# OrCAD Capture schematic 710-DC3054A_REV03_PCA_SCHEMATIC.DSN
size B; title: 3.3V TO 1.8V AT 3A, 4A, 6A AND 6.6MHz LOW EMI BUCK REGULATOR IN A 0.47cm² SOLUTION
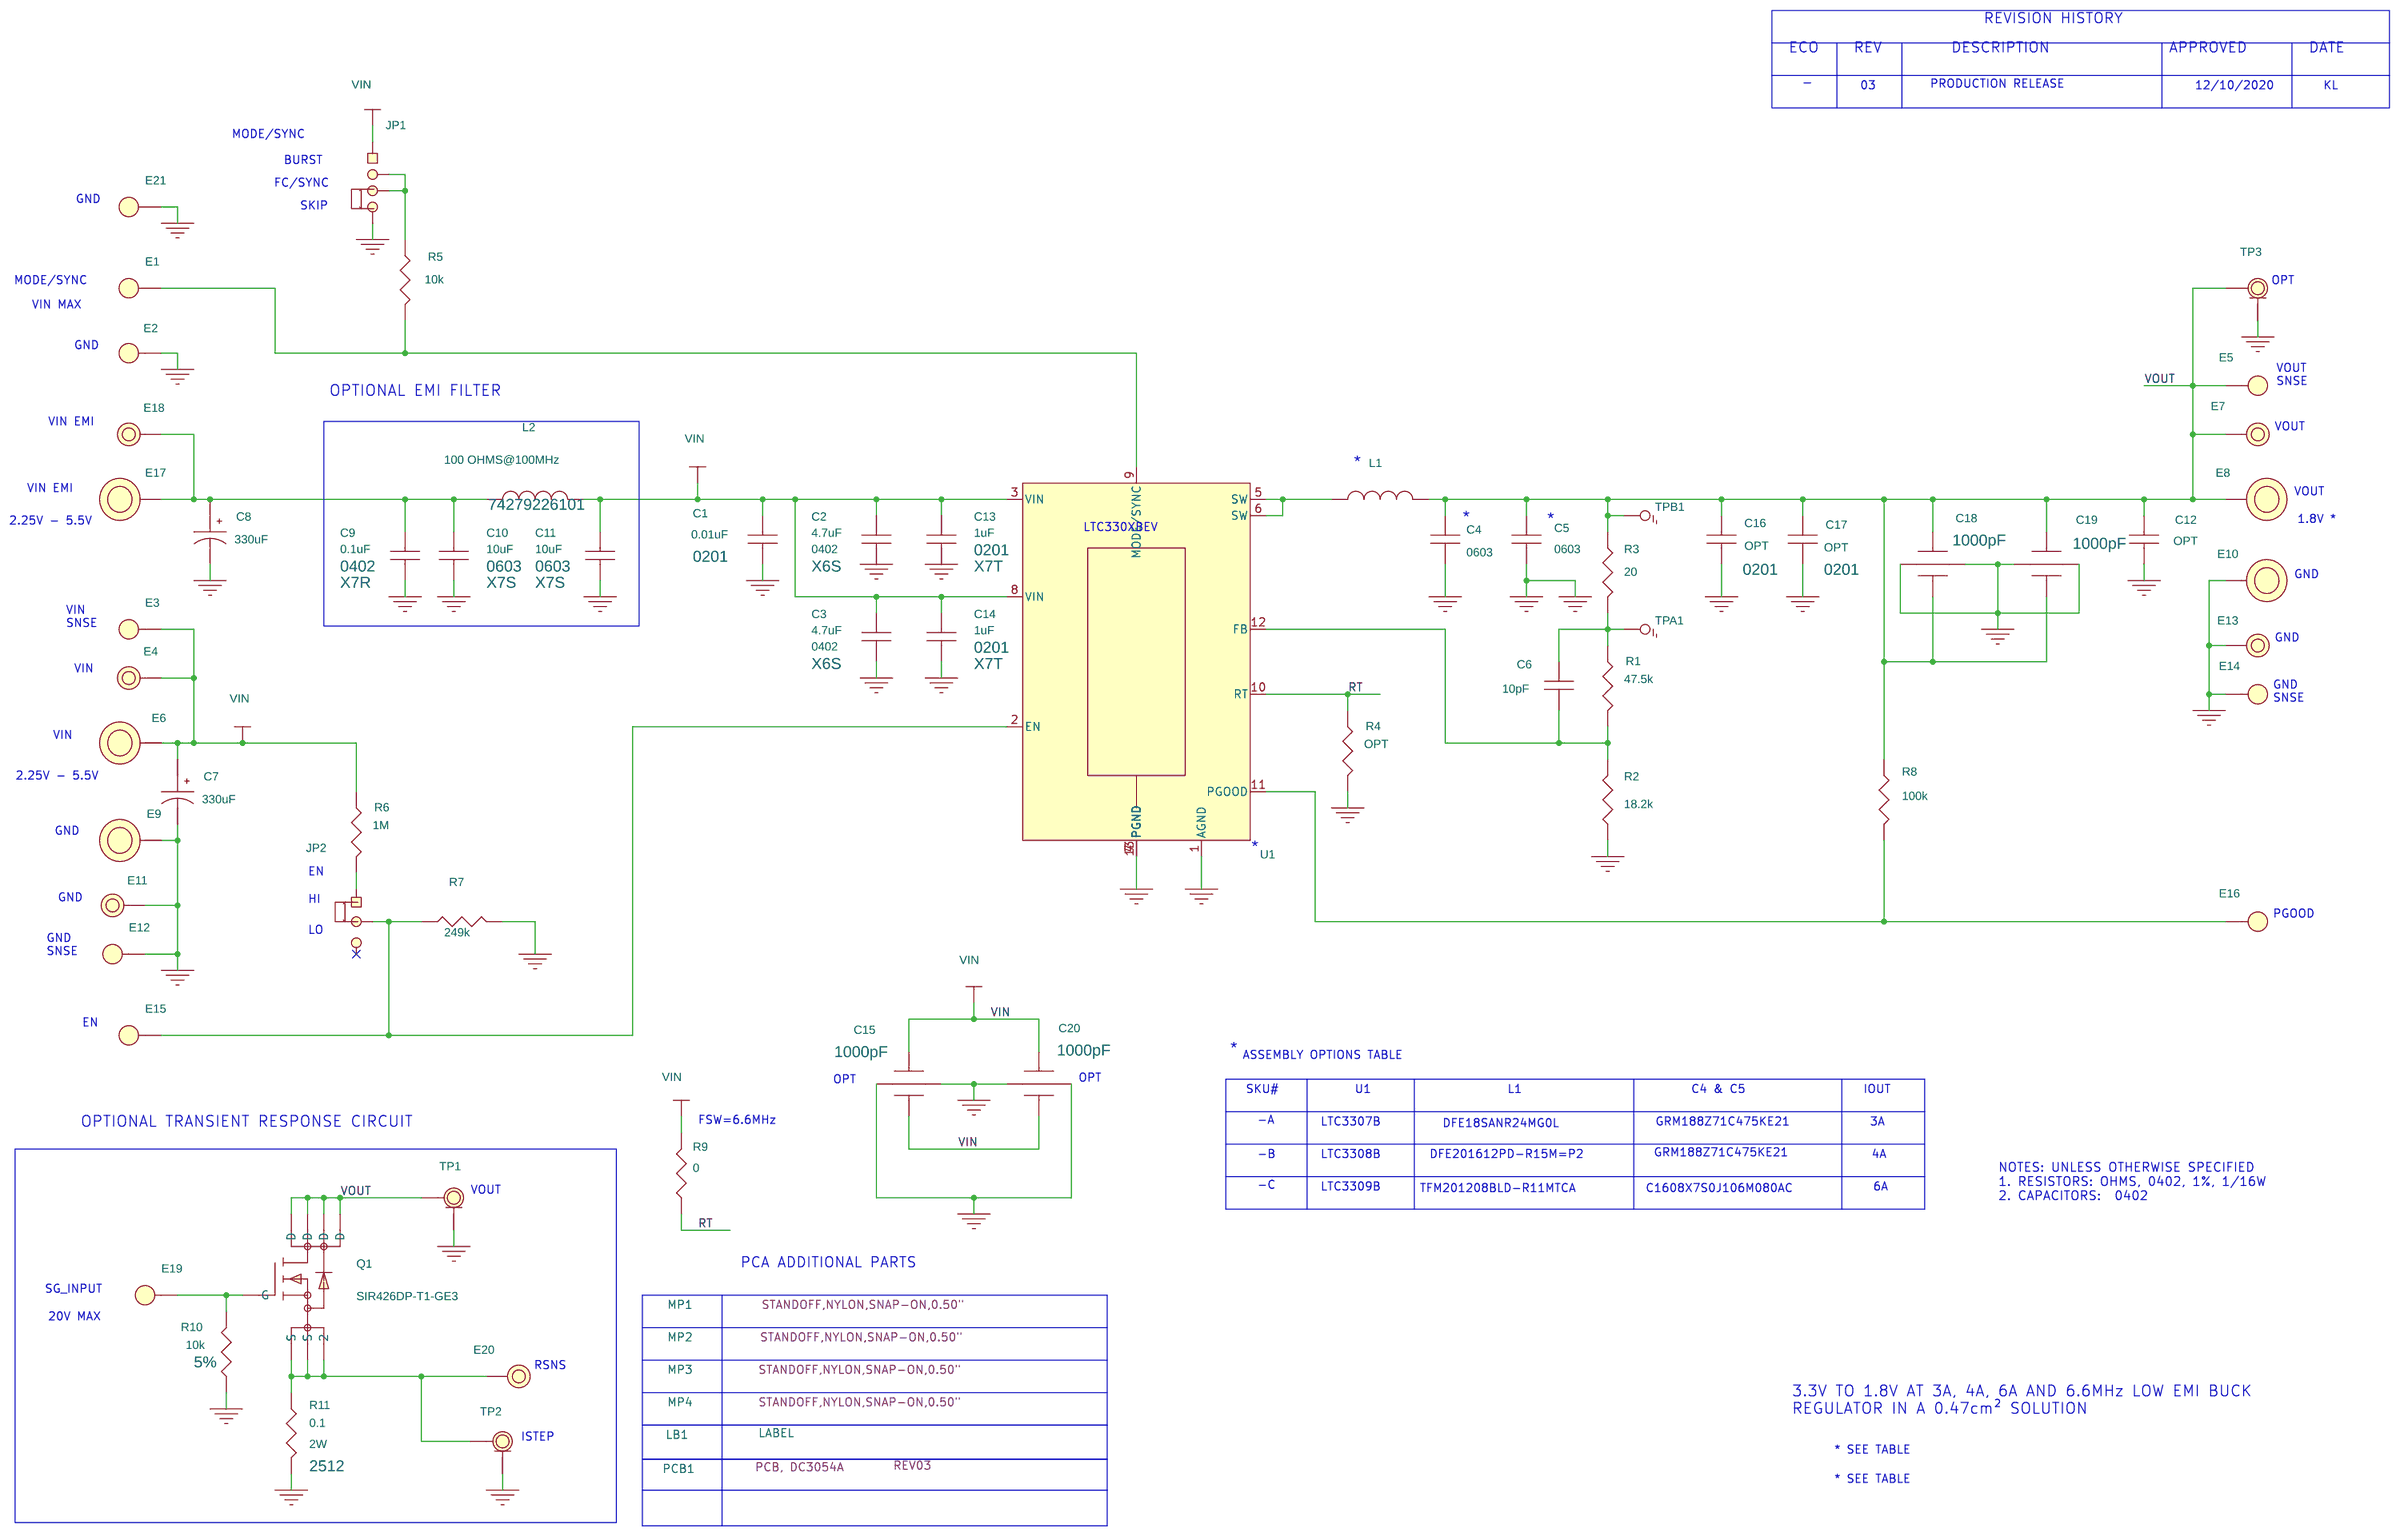
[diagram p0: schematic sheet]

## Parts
C1  0.01uF  [CC0201M]
C2  4.7uF  [CC0402N]
C3  4.7uF  [CC0402N]
C4  10uF  [CC0603N]
C5  10uF  [CC0603N]
C6  10pF  [CC0402N]
C7  330uF  [CAPMP7343N]
C8  330uF  [CAPMP7343N]
C9  0.1uF  [CC0402N]
C10  10uF  [CC0603N]
C11  10uF  [CC0603N]
C12  OPT  [CC0402N]
C13  1uF  [CC0201M]
C14  1uF  [CC0201M]
C15  1000pF  [JOHANSON-X2Y-X07]
C16  OPT  [CC0201M]
C17  OPT  [CC0201M]
C18  1000pF  [JOHANSON-X2Y-X07]
C19  1000pF  [JOHANSON-X2Y-X07]
C20  1000pF  [JOHANSON-X2Y-X07]
E1  TEST POINT  [MILLMAX2308]
E2  TEST POINT  [MILLMAX2308]
E3  TEST POINT  [MILLMAX2308]
E4  TEST POINT  [MILLMAX2501]
E5  TEST POINT  [MILLMAX2308]
E6  BANANA JACK  [KEY-575-4]
E7  TEST POINT  [MILLMAX2501]
E8  BANANA JACK  [KEY-575-4]
E9  BANANA JACK  [KEY-575-4]
E10  BANANA JACK  [KEY-575-4]
E11  TEST POINT  [MILLMAX2501]
E12  TEST POINT  [MILLMAX2308]
E13  TEST POINT  [MILLMAX2501]
E14  TEST POINT  [MILLMAX2308]
E15  TEST POINT  [MILLMAX2308]
E16  TEST POINT  [MILLMAX2308]
E17  BANANA JACK  [KEY-575-4]
E18  TEST POINT  [MILLMAX2501]
E19  TEST POINT  [MILLMAX2308]
E20  TEST POINT  [MILLMAX2501]
E21  TEST POINT  [MILLMAX2308]
JP1  HDR  [JP4X1/079]
JP2  HDR  [HD1X3-079]
L1  150nH  [MURATA-DFE201612PD]
L2  100 OHMS@100MHz  [WURTH-74279226101]
LB1  LABEL  [895-0154_REV01]
MP1  STANDOFF  [KEYSTONE_8829-8834]
MP2  STANDOFF  [KEYSTONE_8829-8834]
MP3  STANDOFF  [KEYSTONE_8829-8834]
MP4  STANDOFF  [KEYSTONE_8829-8834]
PCB1  PCB, DC3054A
Q1  SIR426DP-T1-GE3  [VISHAY_PPAK_SO-8]
R1  47.5k  [CR0402N]
R2  18.2k  [CR0402N]
R3  20  [CR0402N]
R4  OPT  [CR0402N]
R5  10k  [CR0402N]
R6  1M  [CR0402N]
R7  249k  [CR0402N]
R8  100k  [CR0402N]
R9  0  [CR0402N]
R10  10k  [CR0402N]
R11  0.1  [CR2512N]
TP1  U.FL  [HIROSE-FL-R-SMT-1]
TP2  TEST JACK  [TELEDYNE-PK5-2.5MM-113_ALT1]
TP3  U.FL  [HIROSE-FL-R-SMT-1]
TPA1  COPPER FEATURE PAD  [PADSTYLE1]
TPB1  COPPER FEATURE PAD  [PADSTYLE1]
U1  LTC3307B-LQFN  [LTC-LQFN-12-1530]
XJP1  SHUNT
XJP2  SHUNT

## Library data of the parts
C1 = CAP: CAP.,0.01uF,X5R,10V,10%,0201; CLASS: DISCRETE; Dielectric Type: X5R; FPLIST: CC0201N,CC0201L,CC0201M; Inventory Qty: 67000; Manufacturer: MURATA; Manufacturer PN: GRM033R61A103KA01D; PART_NUMBER: 150-0127; Package Size: 0201; Rated Voltage: 10V; Tolerance: 10%
C2 C3 = CAP: CAP.,4.7uF,X6S,6.3V,20%,0402; CLASS: DISCRETE; Dielectric Type: X6S; FPLIST: CC0402N,CC0402L,CC0402M; Inventory Qty: 18600; Manufacturer: MURATA; Manufacturer PN: GRM155C80J475MEAAD; PART_NUMBER: 150-0793; Package Size: 0402; Rated Voltage: 6.3V; Temperature Coefficient: X6S; Tolerance: 20%
C4 C5 C10 C11 = CAP: CAP.,10uF,X7S,6.3V,20%,0603; CLASS: DISCRETE; Dielectric Type: X7S; FPLIST: CC0603N,CC0603L,CC0603M; Inventory Qty: 34800; Manufacturer: TDK; Manufacturer PN: C1608X7S0J106M080AC; PART_NUMBER: 150-1745; Package Size: 0603; Rated Voltage: 6.3V; Tolerance: 20%
C6 = CAP: CAP.,10pF,C0G,50V,5%,0402; CLASS: DISCRETE; Dielectric Type: C0G; FPLIST: CC0402N,CC0402L,CC0402M; Inventory Qty: 13869; Manufacturer: KEMET; Manufacturer PN: C0402C100J5GAC7867; PART_NUMBER: 150-2069; Package Size: 0402; Rated Voltage: 50V; Tolerance: 5%
C7 C8 = CAP_P_ALT: CAP.,330uF,TANT,POSCAP,6.3V,20%,7343,25mOHMS,TPE; CLASS: DISCRETE; Dielectric Type: TANT,POSCAP; Inventory Qty: 3750; Manufacturer: PANASONIC; Manufacturer PN: 6TPE330ML; PART_NUMBER: 150-0529; Package Size: 7343; Rated Voltage: 6.3V; Tolerance: 20%; UserField01: 2400mAms, 25mOHMS
C9 = CAP: CAP.,0.1uF,X7R,10V,10%,0402,AEC-Q200; CLASS: DISCRETE; Dielectric Type: X7R; FPLIST: CC0402N,CC0402L,CC0402M; Inventory Qty: 59100; Manufacturer: MURATA; Manufacturer PN: GCM155R71A104KA55D; PART_NUMBER: 150-1790; Package Size: 0402; Rated Voltage: 10V; Temperature Coefficient: X7R; Tolerance: 10%
C12 = CAP: CAP., OPTION, 0402; CLASS: DISCRETE; PART_NUMBER: 150-3148; Package Size: 0402; Package Type: SMD
C13 C14 = CAP: CAP.,1uF,X7T,6.3V,20%,0201; CLASS: DISCRETE; Dielectric Type: X7T; FPLIST: CC0201N,CC0201L,CC0201M; Inventory Qty: 15600; Manufacturer: MURATA; Manufacturer PN: GRM033D70J105ME01D; PART_NUMBER: 150-1771; Package Size: 0201; Rated Voltage: 6.3V; Tolerance: 20%
C15 C18-C20 = JOHANSON-X2Y: CAP.,1000pF,X7R,50V,20%,0402,3-TERM,X2Y EMI FILTER; CLASS: DISCRETE; Dielectric Type: X7R; Inventory Qty: 16829; Manufacturer: JOHANSON DIELECTRICS; Manufacturer PN: 500X07W102MV4T; PART_NUMBER: 150-1785; Package Size: 0402,3-TERM; Rated Voltage: 50V; Tolerance: 20%
C16 C17 = CAP: CAP., OPTION, 0201; CLASS: DISCRETE; PART_NUMBER: 150-0391; Package Size: 0201; Package Type: SMD
E1-E3 E5 E12 E14-E16 E19 E21 = TEST_POINT_.156_MILL-MAX_2308: TEST POINT,TURRET,0.064" MTG. HOLE,PCB 0.062" THK; CLASS: IO; Inventory Qty: 1142083; Manufacturer PN: 2308-2-00-80-00-00-07-0; PART_NUMBER: 260-0004
E4 E7 E11 E13 E18 E20 = TESTPOINT_.219_MILL-MAX_2501: TEST POINT,TURRET,0.094" MTG. HOLE,PCB 0.062" THK; CLASS: IO; Inventory Qty: 823526; Manufacturer: MILL-MAX; Manufacturer PN: 2501-2-00-80-00-00-07-0; PART_NUMBER: 260-0003
E6 E8-E10 E17 = BANANA_KEYSTONE-575-4: CONN.,BANANA JACK,FEMALE,THT,NON-INSULATED,SWAGE,0.218"; CLASS: IO; Inventory Qty: 203061; Manufacturer: KEYSTONE; Manufacturer PN: 575-4; PART_NUMBER: 250-0428
JP1 = HD1X4-079_ALT: CONN.,HDR,MALE,1x4,2mm,VERT,ST,THT; CLASS: IO; Inventory Qty: 12591; Manufacturer: WURTH ELEKTRONIK; Manufacturer PN: 62000411121; PART_NUMBER: 250-0563
JP2 = 3_PIN_HEADER_.079_SINGLE_ROW_D: CONN.,HDR,MALE,1x3,2mm,VERT,ST,THT; CLASS: IO; Inventory Qty: 22043; Manufacturer: Wurth Elektronik; Manufacturer PN: 62000311121; PART_NUMBER: 250-0484
L1 = IND_ALT: IND.,150nH,PWR,20%,5.2A,18mOHMS,0806,AEC-Q200; CLASS: DISCRETE; Inventory Qty: 3000; Manufacturer: MURATA; Manufacturer PN: DFE201612PD-R15M=P2; PART_NUMBER: 200-0387; Package Size: 0806; Tolerance: 20%
L2 = IND_ALT: IND.,100 OHMS@100MHz,FERRITE BEAD,25%,8A,6mOHMS,1812; CLASS: DISCRETE; Inventory Qty: 3043; Manufacturer: WURTH ELEKTRONIK; Manufacturer PN: 74279226101; PART_NUMBER: 200-0280; Package Size: 1812; Tolerance: 25%
LB1 = BLANK_LABEL: LABEL SPEC, DEMO BOARD SERIAL NUMBER; Inventory Qty: 0; Manufacturer: BRADY; Manufacturer PN: THT-96-717-10; PART_NUMBER: 895-0154
MP1-MP4 = BLANK_MECHANICAL_PART: STANDOFF,NYLON,SNAP-ON,0.50"; CLASS: DISCRETE; FPLIST: KEYSTONE_8829-8834,MTG-8831; Inventory Qty: 9249; Manufacturer: WURTH ELEKTRONIK; Manufacturer PN: 702935000; PART_NUMBER: 763-0020
PCB1 = BLANK_PCB_PART: BOM Notes: REV03; CLASS: DISCRETE; Inventory Qty: 0; Manufacturer: ADI APPROVED SUPPLIER; Manufacturer PN: 600-DC3054A; PART_NUMBER: 600-DC3054A
Q1 = 8P_N-CH_TYPE1A: XSTR.,MOSFET,N-CH,40V,15.9A,PPAK SO-8; CLASS: DISCRETE; Inventory Qty: 20200; Manufacturer: VISHAY; PART_NUMBER: 240-0378; Package Size: PowerPAK® SO-8; Package Type: PPAK SO-8; Polarity: MOSFET N-Channel; Rated Power: 41.7W; Rated Voltage: 40V
R1 = RES: RES.,47.5k OHMS,1%,1/16W,0402; CLASS: DISCRETE; FPLIST: CR0402N,CR0402L,CR0402M; Inventory Qty: 10000; Manufacturer: NIC; Manufacturer PN: NRC04F4752TRF; PART_NUMBER: 100-0390; Package Size: 0402; Rated Power: 1/16W; Temperature Coefficient: 100ppm/C; Tolerance: 1%
R2 = RES: RES.,18.2k OHMS,1%,1/16W,0402,AEC-Q200; CLASS: DISCRETE; FPLIST: CR0402N,CR0402L,CR0402M; Inventory Qty: 20078; Manufacturer: VISHAY; Manufacturer PN: CRCW040218K2FKED; PART_NUMBER: 100-0586; Package Size: 0402; Rated Power: 1/16W; Temperature Coefficient: +/-100PPM; Tolerance: 1%
R3 = RES: RES.,20 OHMS,1%,1/16W,0402,AEC-Q200; CLASS: DISCRETE; FPLIST: CR0402N,CR0402L,CR0402M; Inventory Qty: 29845; Manufacturer: NIC; Manufacturer PN: NRC04F20R0TRF; PART_NUMBER: 100-0250; Package Size: 0402; Rated Power: 1/16W; Temperature Coefficient: 100ppm; Tolerance: 1%
R4 = RES: RES., OPTION, 0402; CLASS: DISCRETE; PART_NUMBER: 100-0357; Package Size: 0402
R5 = RES: RES.,10k OHMS,5%,1/16W,0402,AEC-Q200; CLASS: DISCRETE; FPLIST: CR0402N,CR0402L,CR0402M; Inventory Qty: 64117; Manufacturer: NIC; Manufacturer PN: NRC04J103TRF; PART_NUMBER: 100-0214; Package Size: 0402; Rated Power: 1/16W; Temperature Coefficient: 200ppm; Tolerance: 5%
R6 = RES: RES.,1M OHMS,1%,1/16W,0402,AEC-Q200; CLASS: DISCRETE; FPLIST: CR0402N,CR0402L,CR0402M; Inventory Qty: 86432; Manufacturer: STACKPOLE ELECTRONICS, INC.; Manufacturer PN: RMCF0402FT1M00; PART_NUMBER: 100-2457; Package Size: 0402; Rated Power: 1/16W; Temperature Coefficient: 100ppm; Tolerance: 1%
R7 = RES: RES.,249k OHMS,1%,1/16W,0402,AEC-Q200; CLASS: DISCRETE; FPLIST: CR0402N,CR0402L,CR0402M; Inventory Qty: 26713; Manufacturer: NIC; Manufacturer PN: NRC04F2493TRF; PART_NUMBER: 100-2663; Package Size: 0402; Rated Power: 1/16W; Temperature Coefficient: 100ppm; Tolerance: 1%
R8 = RES: RES.,100k OHMS,5%,1/16W,0402; CLASS: DISCRETE; FPLIST: CR0402N,CR0402L,CR0402M; Inventory Qty: 91623; Manufacturer: YAGEO; Manufacturer PN: RC0402JR-07100KL; PART_NUMBER: 100-0058; Package Size: 0402; Rated Power: 1/16W; Temperature Coefficient: 100ppm/C; Tolerance: 5%
R9 = RES: RES.,0 OHM,1/16W,0402; CLASS: DISCRETE; FPLIST: CR0402N,CR0402L,CR0402M; Inventory Qty: 264417; Manufacturer: ROHM; Manufacturer PN: MCR01MZPJ000; PART_NUMBER: 100-0215; Package Size: 0402; Rated Power: 1/16W
R10 = RES: RES.,10k OHMS,5%,1/10W,0402,AEC-Q200; CLASS: DISCRETE; FPLIST: CR0402N,CR0402L,CR0402M; Inventory Qty: 33211; Manufacturer: PANASONIC; Manufacturer PN: ERJ2GEJ103X; PART_NUMBER: 100-0092; Package Size: 0402; Rated Power: 1/10W; Temperature Coefficient: 200ppm/C; Tolerance: 5%
R11 = RES: RES.,0.1 OHM,1%,2W,2512,SENSE,AEC-Q200; CLASS: DISCRETE; FPLIST: CR2512N,CR2512L,CR2512M; Inventory Qty: 9640; Manufacturer: TT ELECTRONICS; Manufacturer PN: LRC-LR2512LF-01-R100-F; PART_NUMBER: 100-0553; Package Size: 2512; Rated Power: 2W; Temperature Coefficient: 100ppm; Tolerance: 1%
TP1 TP3 = HIROSE-U.FL-R-SMT-1: CONN.,U.FL,RECEPT,ST SMD,0Hz to 6GHz 50Ohm; CLASS: IO; Inventory Qty: 0; Manufacturer: HIROSE ELECTRIC; Manufacturer PN: U.FL-R-SMT-1(10); PART_NUMBER: 250-0939
TP2 = TELEDYNE-PK5-2.5MM-113_ALT1: CONN.,TEST JACK,PLUG,1POS,THT,VERT; CLASS: IO; Inventory Qty: 0; Manufacturer: TELEDYNE; Manufacturer PN: PK5-2.5MM-113; PART_NUMBER: 250-1016
TPA1 TPB1 = PAD_SMALL_FILLED: TESTPOINT, PCB COPPER FEATURE; CLASS: IO; Manufacturer: N/A; Manufacturer PN: N/A; PART_NUMBER: PCBPADS-11
U1 = LTC330XB-LQFN: IC,5V, 3A Synchronous Step-Down Silent Switcher,2x2mm LQFN; CLASS: IC; Inventory Qty: 0; Manufacturer: ANALOG DEVICES; Manufacturer PN: LTC3307BEV#PBF; PART_NUMBER: LTC3307BEV#PBF; Package Size: 12-LGA; Package Type: 2x2mm LQFN
XJP1 XJP2 = CONN_SHUNT_2_POS_2mm: CONN.,SHUNT,FEMALE,2 POS,2mm; CLASS: IO; Inventory Qty: 64675; Manufacturer: Wurth Elektronik; Manufacturer PN: 60800213421; PART_NUMBER: 250-0485

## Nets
GND: C1.2 C2.2 C3.2 C4.2 C5.2 C7.2 C8.2 C9.2 C10.2 C11.2 C12.2 C13.2 C14.2 C15.3(G1) C15.4(G2) C16.2 C17.2 C18.3(G1) C18.4(G2) C19.3(G1) C19.4(G2) C20.3(G1) C20.4(G2) E2.1(A) E9.1 E10.1 E11.1 E12.1(A) E13.1 E14.1(A) E21.1(A) JP1.4 R2.1 R4.2 R7.2 R10.2 R11.2 TP1.2(GND) TP1.3(GND) TP1.4(GND) TP1.5(GND) TP2.2(GND) TP2.3(GND) TP2.4(GND) TP2.5(GND) TP3.2(GND) TP3.3(GND) TP3.4(GND) TP3.5(GND) U1.1(AGND) U1.4(PGND) U1.7(PGND) U1.13(PGND)
VIN: C1.1 C2.1 C3.1 C7.1 C11.1 C13.1 C14.1 C15.1(A) C15.2(B) C20.1(A) C20.2(B) E3.1(A) E4.1 E6.1 JP1.1 L2.2 R6.1 R9.2 U1.3(VIN) U1.8(VIN)
RT: R4.1 R9.1 U1.10(RT)
VOUT: C4.1 C5.1 C12.1 C16.1 C17.1 C18.1(A) C18.2(B) C19.1(A) C19.2(B) E5.1(A) E7.1 E8.1 L1.2 Q1.5(D) Q1.6(D) Q1.7(D) Q1.8(D) R3.1 R8.1 TP1.1 TP3.1 TPB1.1
N16763174: L1.1 U1.5(SW) U1.6(SW)
N16763234: C6.2 R1.2 R2.2 U1.12(FB)
N16763242: E15.1(A) JP2.2 R7.1 U1.2(EN)
N16763412: C6.1 R1.1 R3.2 TPA1.1
N16763484: E16.1(A) R8.2 U1.11(PGOOD)
N16763862: JP2.1 R6.2
N16780618: JP1.2 JP1.3 R5.1
N16781465: E1.1(A) R5.2 U1.9(MODE/SYNC)
N16886451: C8.1 C9.1 C10.1 E17.1 E18.1 L2.1
N16894176: E20.1 Q1.1(S) Q1.2(S) Q1.3(2) R11.1 TP2.1
N16918546: E19.1(A) Q1.4(G) R10.1

Not connected (* = marked no-connect by the designer): JP2 3*

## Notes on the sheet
- REVISION HISTORY
- ECO
- REV
- DESCRIPTION
- APPROVED
- DATE
- -
- PRODUCTION RELEASE
- 03
- 12/10/2020
- KL
- MODE/SYNC
- BURST
- GND
- FC/SYNC
- SKIP
- MODE/SYNC
- OPT
- VIN MAX
- GND
- VOUT
  SNSE
- OPTIONAL EMI FILTER
- VIN EMI
- VOUT
- *
- VIN EMI
- VOUT
- 2.25V - 5.5V
- *
- *
- 1.8V *
- LTC330XBEV
- GND
- VIN
  SNSE
- GND
- VIN
- GND
  SNSE
- VIN
- 2.25V - 5.5V
- GND
- *
- EN
- GND
- HI
- PGOOD
- GND
  SNSE
- LO
- EN
- *
- ASSEMBLY OPTIONS TABLE
- OPT
- OPT
- SKU#
- U1
- L1
- C4 & C5
- IOUT
- OPTIONAL TRANSIENT RESPONSE CIRCUIT
- FSW=6.6MHz
- -A
- LTC3307B
- DFE18SANR24MG0L
- GRM188Z71C475KE21
- 3A
- -B
- LTC3308B
- DFE201612PD-R15M=P2
- GRM188Z71C475KE21
- 4A
- NOTES: UNLESS OTHERWISE SPECIFIED
  1. RESISTORS: OHMS, 0402, 1%, 1/16W
  2. CAPACITORS:  0402
- VOUT
- -C
- LTC3309B
- TFM201208BLD-R11MTCA
- C1608X7S0J106M080AC
- 6A
- PCA ADDITIONAL PARTS
- SG_INPUT
- 20V MAX
- RSNS
- 3.3V TO 1.8V AT 3A, 4A, 6A AND 6.6MHz LOW EMI BUCK
  REGULATOR IN A 0.47cm² SOLUTION
- ISTEP
- * SEE TABLE
- * SEE TABLE
